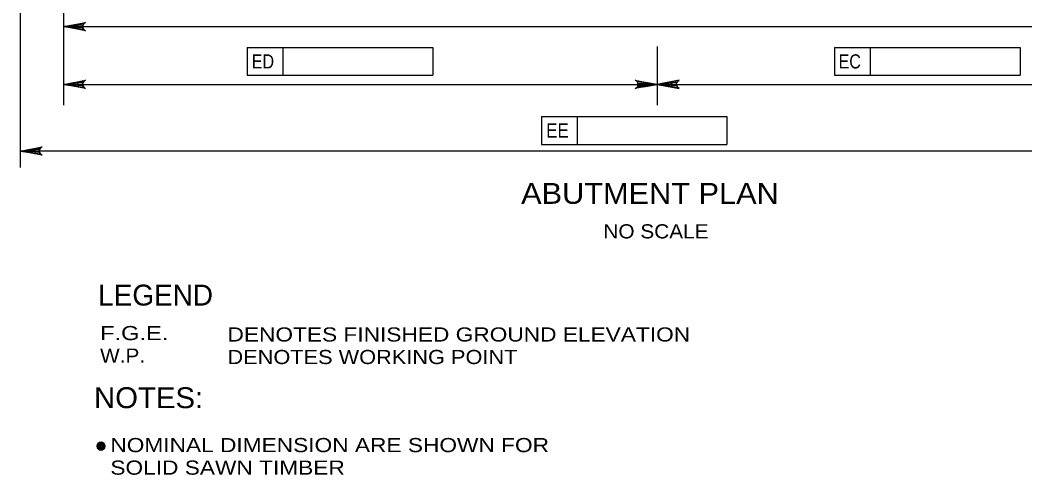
# Model space of a CAD drawing. Extents: x -6.4 to 73.1, y -66 to 0.
# Drawn here: x 7.57 to 16.1, y -54.62 to -50.76 of the extents above; entities that cross this region are included whole.
import ezdxf
from ezdxf.enums import TextEntityAlignment as Align

# ---------------------------------------------------------------- set-up
doc = ezdxf.new("R2010")
doc.units = 0
doc.header["$LTSCALE"] = 0.048
doc.layers.add('5', color=7, linetype='Continuous', lineweight=25)

msp = doc.modelspace()

# ---------------------------------------------------------------- hatches: boundary and pattern name
at = {"layer": '5'}
for points in [[(8.05567, -50.79925), (8.05567, -50.83858), (7.93758, -50.81892)], [(8.05567, -51.28958), (8.05567, -51.329), (7.93758, -51.30925)], [(12.85917, -51.28958), (12.85917, -51.329), (12.97733, -51.30925)], [(13.09542, -51.28958), (13.09542, -51.329), (12.97733, -51.30925)]]:
    msp.add_hatch(color=256, dxfattribs=at).paths.add_polyline_path(points)

# ---------------------------------------------------------------- linework, layer by layer
for p, q in [((7.93758, -49.07617), (7.93758, -51.48642)), ((7.56925, -49.45875), (7.56925, -52.01483)), ((7.93758, -50.81892), (17.92275, -50.81892)), ((9.49658, -50.99642), (11.07142, -50.99642)), ((9.49658, -50.99642), (9.49658, -51.23267)), ((9.799, -50.99642), (9.799, -51.23267)), ((11.07142, -50.99642), (11.07142, -51.23267)), ((12.97733, -50.98867), (12.97733, -51.48642)), ((14.48158, -50.99642), (16.05642, -50.99642)), ((14.48158, -50.99642), (14.48158, -51.23267)), ((14.78408, -50.99642), (14.78408, -51.23267)), ((16.05642, -50.99642), (16.05642, -51.23267)), ((9.49658, -51.23267), (11.07142, -51.23267)), ((14.48158, -51.23267), (16.05642, -51.23267)), ((7.93758, -51.30925), (12.85917, -51.30925)), ((13.09542, -51.30925), (17.92275, -51.30925)), ((11.99392, -51.58233), (13.56875, -51.58233)), ((11.99392, -51.58233), (11.99392, -51.81858)), ((12.29642, -51.58233), (12.29642, -51.81858)), ((13.56875, -51.58233), (13.56875, -51.81858)), ((11.99392, -51.81858), (13.56875, -51.81858)), ((18.34475, -51.87508), (7.56925, -51.87508))]:
    msp.add_line(p, q, dxfattribs=at)
for points in [[(7.93758, -50.81892), (8.124, -50.784), (8.10967, -50.79392), (8.10225, -50.80642), (8.10008, -50.81892), (8.10225, -50.83142), (8.10967, -50.84392), (8.124, -50.85383), (7.93758, -50.81892), (8.10967, -50.84392), (8.10225, -50.83142), (7.93758, -50.81892), (8.10008, -50.81892), (8.10225, -50.80642), (7.93758, -50.81892), (8.10967, -50.79392)], [(7.93758, -51.30925), (8.124, -51.27433), (8.10967, -51.28425), (8.10225, -51.29675), (8.10008, -51.30925), (8.10225, -51.32175), (8.10967, -51.33425), (8.124, -51.34417), (7.93758, -51.30925), (8.10967, -51.33425), (8.10225, -51.32175), (7.93758, -51.30925), (8.10008, -51.30925), (8.10225, -51.29675), (7.93758, -51.30925), (8.10967, -51.28425)], [(12.97733, -51.30925), (12.79092, -51.34417), (12.80525, -51.33425), (12.81267, -51.32175), (12.81483, -51.30925), (12.81267, -51.29675), (12.80525, -51.28425), (12.79092, -51.27433), (12.97733, -51.30925), (12.80525, -51.28425), (12.81267, -51.29675), (12.97733, -51.30925), (12.81483, -51.30925), (12.81267, -51.32175), (12.97733, -51.30925), (12.80525, -51.33425)], [(12.97733, -51.30925), (13.16375, -51.34417), (13.14942, -51.33425), (13.142, -51.32175), (13.13983, -51.30925), (13.142, -51.29675), (13.14942, -51.28425), (13.16375, -51.27433), (12.97733, -51.30925), (13.14942, -51.28425), (13.142, -51.29675), (12.97733, -51.30925), (13.13983, -51.30925), (13.142, -51.32175), (12.97733, -51.30925), (13.14942, -51.33425)], [(7.56925, -51.87508), (7.75567, -51.84017), (7.74133, -51.85008), (7.73392, -51.86258), (7.73175, -51.87508), (7.73392, -51.88758), (7.74133, -51.90008), (7.75567, -51.91), (7.56925, -51.87508), (7.74133, -51.90008), (7.73392, -51.88758), (7.56925, -51.87508), (7.73175, -51.87508), (7.73392, -51.86258), (7.56925, -51.87508), (7.74133, -51.85008)]]:
    msp.add_lwpolyline(points, dxfattribs=at)
for points in [[(8.05567, -50.79925), (8.05567, -50.83858), (7.93758, -50.81892)], [(8.05567, -51.28958), (8.05567, -51.329), (7.93758, -51.30925)], [(12.85917, -51.28958), (12.85917, -51.329), (12.97733, -51.30925)], [(13.09542, -51.28958), (13.09542, -51.329), (12.97733, -51.30925)]]:
    msp.add_lwpolyline(points, close=True, dxfattribs=at)
at = {"layer": '5', "lineweight": 35}
for radius in [0.03333, 0.025, 0.01667, 0.00833]:
    msp.add_circle((8.25619, -54.37873), radius, dxfattribs=at)

# ---------------------------------------------------------------- texts
at = {"layer": '5'}
for s, height, width, p in [('ED', 0.12, 0.85, (9.63042, -51.17458)), ('EC', 0.12, 0.85, (14.61067, -51.17458)), ('EE', 0.12, 0.9, (12.13004, -51.7605)), ('ABUTMENT PLAN', 0.1772, 1.1, (12.91517, -52.32292)), ('NO SCALE', 0.12, 1.1, (12.96604, -52.61625))]:
    msp.add_text(s, height=height, dxfattribs=dict(at, width=width)).set_placement(p, align=Align.CENTER)
msp.add_text('LEGEND', height=0.1772, dxfattribs=at).set_placement((8.23217, -53.18583))
for s, height, width, p in [('F.G.E.', 0.12, 1.25, (8.248, -53.4795)), ('DENOTES FINISHED GROUND ELEVATION', 0.12, 1.2, (9.32958, -53.49108)), ('W.P.', 0.12, 1.1, (8.248, -53.67067)), ('DENOTES WORKING POINT', 0.12, 1.15, (9.32958, -53.68233)), ('NOTES:', 0.1772, 1.05, (8.19675, -54.05625)), ('NOMINAL DIMENSION ARE SHOWN FOR ', 0.12, 1.2, (8.33525, -54.42958)), ('SOLID SAWN TIMBER', 0.12, 1.2, (8.33525, -54.62083))]:
    msp.add_text(s, height=height, dxfattribs=dict(at, width=width)).set_placement(p)

doc.saveas('drawing.dxf')
